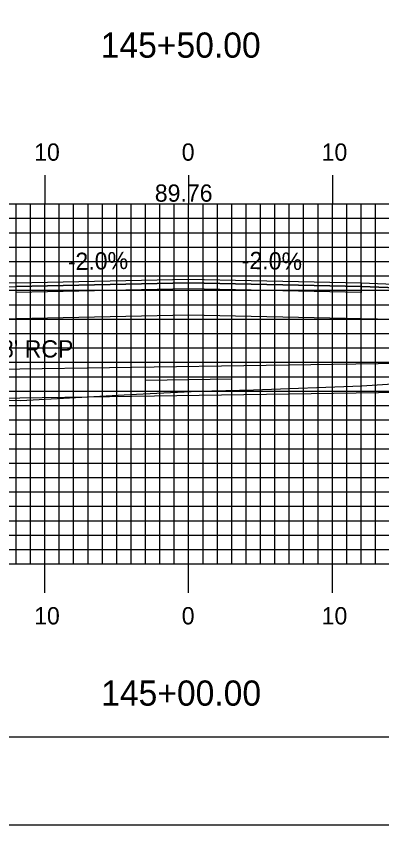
# Model space of a CAD drawing. Extents: x 1777531 to 1777875, y 442591 to 442811.
# Drawn here: x 1777685.3 to 1777710.7, y 442590.5 to 442646.7 of the extents above; entities that cross this region are included whole.
import ezdxf

# ---------------------------------------------------------------- set-up
doc = ezdxf.new("R2010")
doc.units = 0
for name, color, linetype in [('ANNOTATION', 7, 'Continuous'), ('BORDER', 7, 'Continuous'), ('D_Drainage_Culvert', 7, 'Continuous'), ('D_Drainage_Text', 7, 'Continuous'), ('D_Roadway_Centerline', 7, 'Continuous'), ('D_Roadway_Centerline_Text', 7, 'Continuous'), ('D_Roadway_Edge_Shoulder', 7, 'Continuous'), ('D_Roadway_Edge_TW', 7, 'Continuous'), ('D_Roadway_Pavement', 7, 'Continuous'), ('D_Roadway_SubGrade', 7, 'Continuous'), ('H_V ANNOTATION', 7, 'Continuous'), ('MAJOR', 7, 'Continuous'), ('MINOR', 7, 'Continuous'), ('PLOT BOUNDARY', 7, 'Continuous'), ('S_Roadway_Centerline', 7, 'Continuous')]:
    doc.layers.add(name, color=color, linetype=linetype)

msp = doc.modelspace()

# ---------------------------------------------------------------- linework, layer by layer
at = {"layer": 'BORDER'}
msp.add_lwpolyline([(1777547.677, 442596.665), (1777867.677, 442596.665), (1777867.677, 442806.665), (1777547.677, 442806.665)], close=True, dxfattribs=at)
at = {"layer": 'D_Drainage_Culvert'}
for p, q in [((1777649.74, 442621.669), (1777737.74, 442622.989)), ((1777700.277, 442621.49), (1777694.277, 442621.4)), ((1777649.77, 442619.669), (1777737.77, 442620.989))]:
    msp.add_line(p, q, dxfattribs=at)
at = {"layer": 'D_Roadway_Edge_Shoulder'}
for points in [[(1777685.277, 442628.189), (1777673.932, 442627.736), (1777673.932, 442627.486), (1777685.277, 442627.939)], [(1777709.277, 442628.189), (1777717.277, 442627.869), (1777717.277, 442627.619), (1777709.277, 442627.939)]]:
    msp.add_lwpolyline(points, close=True, dxfattribs=at)
at = {"layer": 'D_Roadway_Edge_TW'}
msp.add_lwpolyline([(1777685.277, 442627.939), (1777685.277, 442628.189), (1777697.277, 442628.429), (1777709.277, 442628.189), (1777709.277, 442627.939), (1777697.277, 442628.179)], close=True, dxfattribs=at)
at = {"layer": 'D_Roadway_Pavement'}
msp.add_lwpolyline([(1777685.277, 442627.523), (1777685.277, 442627.939), (1777697.277, 442628.179), (1777709.277, 442627.939), (1777709.277, 442627.523), (1777697.277, 442627.763)], close=True, dxfattribs=at)
at = {"layer": 'D_Roadway_SubGrade'}
msp.add_lwpolyline([(1777685.277, 442625.689), (1777664.049, 442625.265), (1777673.932, 442627.736), (1777673.932, 442627.486), (1777685.277, 442627.939), (1777697.277, 442628.179), (1777709.277, 442627.939), (1777717.277, 442627.619), (1777717.277, 442627.869), (1777727.451, 442625.326), (1777709.277, 442625.689), (1777697.277, 442625.929)], close=True, dxfattribs=at)
at = {"layer": 'MAJOR'}
for p, q in [((1777687.277, 442635.669), (1777687.277, 442633.665)), ((1777697.277, 442635.669), (1777697.277, 442633.665)), ((1777707.277, 442635.669), (1777707.277, 442633.665)), ((1777557.277, 442633.665), (1777837.277, 442633.665)), ((1777557.277, 442633.665), (1777837.277, 442633.665)), ((1777687.277, 442608.665), (1777687.277, 442633.665)), ((1777697.277, 442608.665), (1777697.277, 442633.665)), ((1777707.277, 442608.665), (1777707.277, 442633.665)), ((1777557.277, 442628.665), (1777837.277, 442628.665)), ((1777557.277, 442623.665), (1777837.277, 442623.665)), ((1777557.277, 442618.665), (1777837.277, 442618.665)), ((1777557.277, 442613.665), (1777837.277, 442613.665)), ((1777557.277, 442608.665), (1777837.277, 442608.665)), ((1777557.277, 442608.665), (1777837.277, 442608.665)), ((1777687.277, 442606.661), (1777687.277, 442608.665)), ((1777697.277, 442606.661), (1777697.277, 442608.665)), ((1777707.277, 442606.661), (1777707.277, 442608.665))]:
    msp.add_line(p, q, dxfattribs=at)
at = {"layer": 'MINOR'}
for p, q in [((1777685.277, 442608.665), (1777685.277, 442633.665)), ((1777686.277, 442608.665), (1777686.277, 442633.665)), ((1777688.277, 442608.665), (1777688.277, 442633.665)), ((1777689.277, 442608.665), (1777689.277, 442633.665)), ((1777690.277, 442608.665), (1777690.277, 442633.665)), ((1777691.277, 442608.665), (1777691.277, 442633.665)), ((1777692.277, 442608.665), (1777692.277, 442633.665)), ((1777693.277, 442608.665), (1777693.277, 442633.665)), ((1777694.277, 442608.665), (1777694.277, 442633.665)), ((1777695.277, 442608.665), (1777695.277, 442633.665)), ((1777696.277, 442608.665), (1777696.277, 442633.665)), ((1777698.277, 442608.665), (1777698.277, 442633.665)), ((1777699.277, 442608.665), (1777699.277, 442633.665)), ((1777700.277, 442608.665), (1777700.277, 442633.665)), ((1777701.277, 442608.665), (1777701.277, 442633.665)), ((1777702.277, 442608.665), (1777702.277, 442633.665)), ((1777703.277, 442608.665), (1777703.277, 442633.665)), ((1777704.277, 442608.665), (1777704.277, 442633.665)), ((1777705.277, 442608.665), (1777705.277, 442633.665)), ((1777706.277, 442608.665), (1777706.277, 442633.665)), ((1777708.277, 442608.665), (1777708.277, 442633.665)), ((1777709.277, 442608.665), (1777709.277, 442633.665)), ((1777710.277, 442608.665), (1777710.277, 442633.665)), ((1777557.277, 442632.665), (1777837.277, 442632.665)), ((1777557.277, 442631.665), (1777837.277, 442631.665)), ((1777557.277, 442630.665), (1777837.277, 442630.665)), ((1777557.277, 442629.665), (1777837.277, 442629.665)), ((1777557.277, 442627.665), (1777837.277, 442627.665)), ((1777557.277, 442626.665), (1777837.277, 442626.665)), ((1777557.277, 442625.665), (1777837.277, 442625.665)), ((1777557.277, 442624.665), (1777837.277, 442624.665)), ((1777557.277, 442622.665), (1777837.277, 442622.665)), ((1777557.277, 442621.665), (1777837.277, 442621.665)), ((1777557.277, 442620.665), (1777837.277, 442620.665)), ((1777557.277, 442619.665), (1777837.277, 442619.665)), ((1777557.277, 442617.665), (1777837.277, 442617.665)), ((1777557.277, 442616.665), (1777837.277, 442616.665)), ((1777557.277, 442615.665), (1777837.277, 442615.665)), ((1777557.277, 442614.665), (1777837.277, 442614.665)), ((1777557.277, 442612.665), (1777837.277, 442612.665)), ((1777557.277, 442611.665), (1777837.277, 442611.665)), ((1777557.277, 442610.665), (1777837.277, 442610.665)), ((1777557.277, 442609.665), (1777837.277, 442609.665))]:
    msp.add_line(p, q, dxfattribs=at)
at = {"layer": 'PLOT BOUNDARY'}
msp.add_lwpolyline([(1777531.49, 442590.547), (1777871.49, 442590.547), (1777871.49, 442810.547), (1777531.49, 442810.547)], close=True, dxfattribs=at)
at = {"layer": 'S_Roadway_Centerline'}
msp.add_lwpolyline([(1777633.64, 442619.257), (1777646.456, 442619.566), (1777655.751, 442619.741), (1777669.078, 442620.093), (1777673.828, 442620.29), (1777677.649, 442620.237), (1777685.596, 442620.01), (1777693.64, 442620.461), (1777697.922, 442620.667), (1777701.791, 442620.763), (1777709.331, 442621.037), (1777724.017, 442621.975), (1777731.905, 442622.099), (1777741.337, 442622.578), (1777744.76, 442622.674), (1777747.718, 442622.714), (1777756.235, 442622.757)], dxfattribs=at)

# ---------------------------------------------------------------- texts
at = {"layer": 'ANNOTATION'}
for rotation, p in [(1.1458, (1777688.883, 442629.062)), (358.8542, (1777700.963, 442629.156))]:
    msp.add_text('-2.0%', height=1.2, rotation=rotation, dxfattribs=at).set_placement(p)
at = {"layer": 'D_Drainage_Text'}
msp.add_text('24" X 88\' RCP', height=1.2, dxfattribs=at).set_placement((1777679.015, 442622.998))
at = {"layer": 'D_Roadway_Centerline'}
for s, p in [('C', (1777697.272, 442628.429)), ('L', (1777697.277, 442628.422))]:
    msp.add_text(s, height=0.0146, dxfattribs=at).set_placement(p)
at = {"layer": 'D_Roadway_Centerline_Text'}
msp.add_text('89.76', height=1.2, dxfattribs=at).set_placement((1777694.922, 442633.819))
at = {"layer": 'H_V ANNOTATION'}
for s, height, p in [('145+50.00', 1.75, (1777691.159, 442643.821)), ('10', 1.2, (1777686.528, 442636.665)), ('0', 1.2, (1777696.795, 442636.665)), ('10', 1.2, (1777706.528, 442636.665)), ('10', 1.2, (1777686.528, 442604.465)), ('0', 1.2, (1777696.795, 442604.465)), ('10', 1.2, (1777706.528, 442604.465)), ('145+00.00', 1.75, (1777691.191, 442598.821))]:
    msp.add_text(s, height=height, dxfattribs=at).set_placement(p)

doc.saveas('drawing.dxf')
